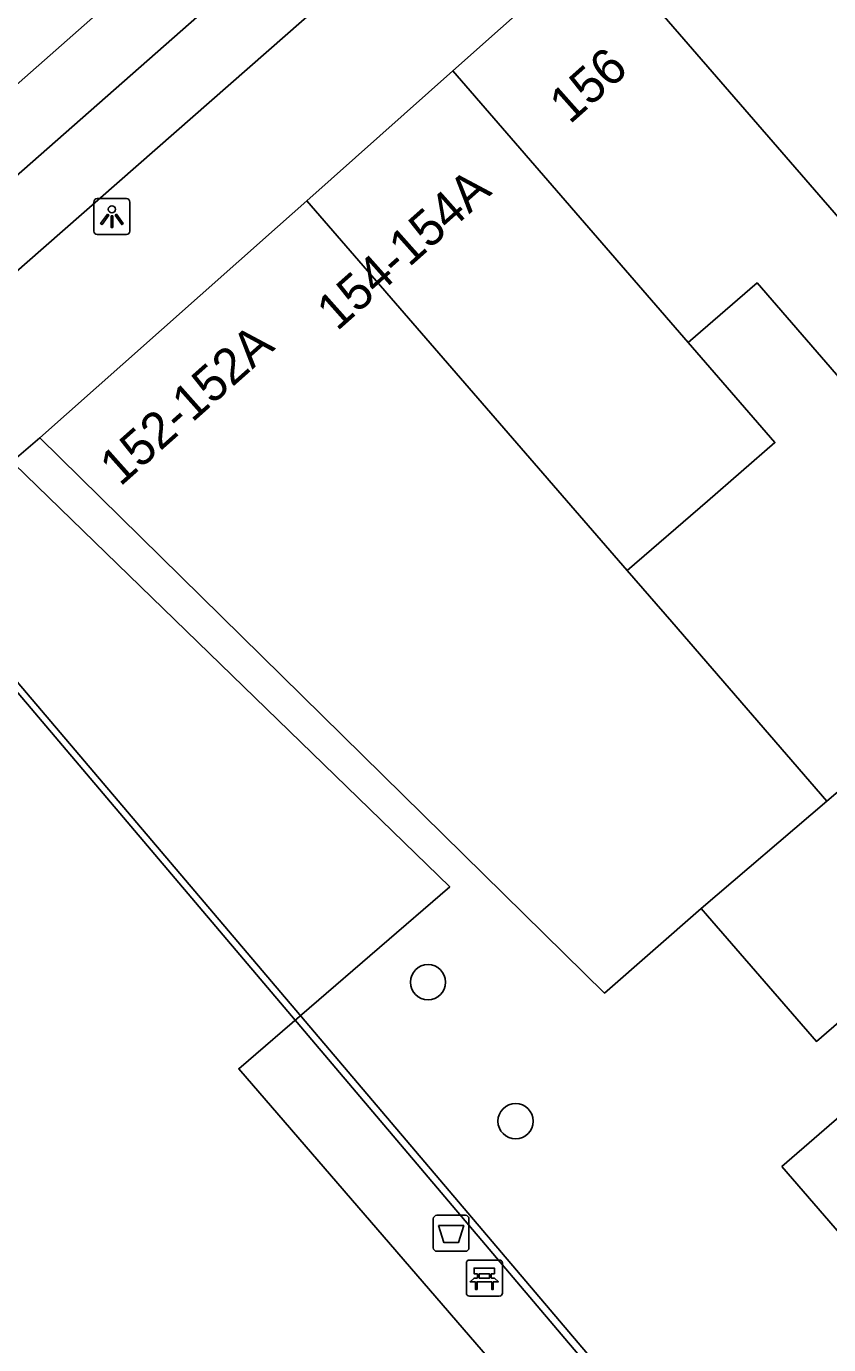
# Model space of a CAD drawing. Extents: x 162172 to 163187, y 382874 to 383684.
# Drawn here: x 162599.47 to 162621.75, y 383429.73 to 383466.36 of the extents above; entities that cross this region are included whole.
import ezdxf

# ---------------------------------------------------------------- set-up
doc = ezdxf.new("R2010")
doc.units = 0
for name, color, linetype in [('IMGEO_Afvalbak', 7, 'Continuous'), ('IMGEO_Bank', 7, 'Continuous'), ('IMGEO_Boom', 7, 'Continuous'), ('IMGEO_Lichtpunt', 7, 'Continuous'), ('IMGEO_Muur', 7, 'Continuous'), ('IMGEO_Pand', 7, 'Continuous'), ('IMGEO_Pand_nummerreeks', 7, 'Continuous'), ('IMGEO_Pand_vergunning_verleend', 7, 'Continuous'), ('IMGEO_Rijbaan_lokaal_gesloten', 7, 'Continuous'), ('IMGEO_Voetpad_open', 7, 'Continuous')]:
    doc.layers.add(name, color=color, linetype=linetype)

msp = doc.modelspace()

# ---------------------------------------------------------------- linework, layer by layer
at = {"layer": 'IMGEO_Afvalbak'}
for p, q in [((162610.771, 383432.422), (162610.771, 383433.222)), ((162610.771, 383433.222), (162610.771, 383432.422)), ((162610.871, 383433.322), (162611.661, 383433.322)), ((162611.661, 383433.322), (162610.871, 383433.322)), ((162611.761, 383433.222), (162611.761, 383432.422)), ((162611.761, 383432.422), (162611.761, 383433.222)), ((162611.661, 383432.322), (162610.871, 383432.322)), ((162610.871, 383432.322), (162611.661, 383432.322))]:
    msp.add_line(p, q, dxfattribs=at)
msp.add_lwpolyline([(162610.914, 383433.036), (162611.618, 383433.036), (162611.469, 383432.566), (162611.063, 383432.566), (162610.914, 383433.036)], dxfattribs=at)
for centre, start, end in [((162610.871, 383433.222), 90, 180), ((162610.871, 383433.222), 90, 180), ((162611.661, 383433.222), 0, 90), ((162611.661, 383433.222), 360, 90), ((162610.871, 383432.422), 180, 270), ((162610.871, 383432.422), 180, 270), ((162611.661, 383432.422), 270, 0), ((162611.661, 383432.422), 270, 0)]:
    msp.add_arc(centre, 0.1, start, end, dxfattribs=at)
at = {"layer": 'IMGEO_Bank'}
for p, q in [((162611.763, 383432.079), (162612.604, 383432.079)), ((162612.604, 383432.079), (162611.763, 383432.079)), ((162611.688, 383431.154), (162611.688, 383431.995)), ((162611.688, 383431.995), (162611.688, 383431.154)), ((162611.997, 383431.585), (162611.997, 383431.691)), ((162612.041, 383431.691), (162612.041, 383431.585)), ((162612.329, 383431.697), (162612.047, 383431.697)), ((162612.335, 383431.585), (162612.335, 383431.691)), ((162612.379, 383431.691), (162612.379, 383431.585)), ((162612.688, 383432.004), (162612.688, 383431.163)), ((162612.688, 383431.163), (162612.688, 383432.004)), ((162612.385, 383431.477), (162611.992, 383431.477)), ((162612.047, 383431.579), (162612.329, 383431.579)), ((162612.613, 383431.079), (162611.772, 383431.079)), ((162611.772, 383431.079), (162612.613, 383431.079))]:
    msp.add_line(p, q, dxfattribs=at)
for points in [[(162611.991, 383431.697), (162611.905, 383431.697), (162611.905, 383431.858), (162612.468, 383431.858), (162612.468, 383431.697), (162612.385, 383431.697)], [(162611.935, 383431.477), (162611.793, 383431.477), (162611.905, 383431.579), (162611.991, 383431.579)], [(162611.985, 383431.47), (162611.985, 383431.263), (162611.942, 383431.263), (162611.942, 383431.47)], [(162612.385, 383431.579), (162612.468, 383431.579), (162612.58, 383431.477), (162612.441, 383431.477)], [(162612.435, 383431.47), (162612.435, 383431.263), (162612.391, 383431.263), (162612.391, 383431.47)]]:
    msp.add_lwpolyline(points, dxfattribs=at)
for centre, radius, start, end in [((162611.766, 383432.001), 0.0779, 92.4484, 184.2845), ((162611.766, 383432.001), 0.0779, 92.4484, 184.2845), ((162612.61, 383432.001), 0.0779, 2.4484, 94.2845), ((162612.61, 383432.001), 0.0779, 2.4484, 94.2845), ((162611.99, 383431.69), 0.00671, 2.8957, 87.1043), ((162612.047, 383431.69), 0.00671, 92.8957, 177.1043), ((162612.329, 383431.69), 0.00671, 2.8957, 87.1043), ((162612.386, 383431.69), 0.00671, 92.8957, 177.1043), ((162611.935, 383431.47), 0.00671, 2.8957, 87.1043), ((162611.992, 383431.47), 0.00671, 92.8957, 177.1043), ((162611.99, 383431.586), 0.00671, 272.8957, 357.1043), ((162612.047, 383431.586), 0.00671, 182.8957, 267.1043), ((162612.329, 383431.586), 0.00671, 272.8957, 357.1043), ((162612.386, 383431.586), 0.00671, 182.8957, 267.1043), ((162612.384, 383431.47), 0.00671, 2.8957, 87.1043), ((162612.441, 383431.47), 0.00671, 92.8957, 177.1043), ((162611.766, 383431.157), 0.0779, 182.4484, 274.2845), ((162611.766, 383431.157), 0.0779, 182.4484, 274.2845), ((162612.61, 383431.157), 0.0779, 272.4484, 4.2845), ((162612.61, 383431.157), 0.0779, 272.4484, 4.2845)]:
    msp.add_arc(centre, radius, start, end, dxfattribs=at)
at = {"layer": 'IMGEO_Boom'}
for centre in [(162610.624, 383439.8), (162613.055, 383435.938)]:
    msp.add_circle(centre, 0.489, dxfattribs=at)
at = {"layer": 'IMGEO_Lichtpunt'}
for p, q in [((162601.346, 383461.478), (162601.346, 383460.671)), ((162601.346, 383461.478), (162601.346, 383460.671)), ((162602.248, 383461.573), (162601.44, 383461.573)), ((162602.248, 383461.573), (162601.44, 383461.573)), ((162602.342, 383460.671), (162602.342, 383461.478)), ((162602.342, 383460.671), (162602.342, 383461.478)), ((162601.44, 383460.577), (162602.248, 383460.577)), ((162601.44, 383460.577), (162602.248, 383460.577))]:
    msp.add_line(p, q, dxfattribs=at)
for points in [[(162601.72, 383461.142), (162601.759, 383461.114), (162601.571, 383460.852), (162601.533, 383460.879), (162601.72, 383461.142)], [(162601.822, 383461.094), (162601.869, 383461.094), (162601.869, 383460.772), (162601.822, 383460.772), (162601.822, 383461.094)], [(162601.932, 383461.114), (162601.97, 383461.141), (162602.157, 383460.879), (162602.118, 383460.851), (162601.932, 383461.114)]]:
    msp.add_lwpolyline(points, dxfattribs=at)
msp.add_circle((162601.845, 383461.276), 0.0994, dxfattribs=at)
for centre, start, end in [((162601.44, 383461.478), 90, 180), ((162601.44, 383461.478), 90, 180), ((162602.248, 383461.478), 0, 90), ((162602.248, 383461.478), 0, 90), ((162601.44, 383460.671), 180, 270), ((162601.44, 383460.671), 180, 270), ((162602.248, 383460.671), 270, 0), ((162602.248, 383460.671), 270, 360)]:
    msp.add_arc(centre, 0.0946, start, end, dxfattribs=at)
at = {"layer": 'IMGEO_Muur'}
for points in [[(162607.288, 383420.314), (162607.178, 383420.445), (162616.112, 383427.895), (162596.004, 383451.649)], [(162596.138, 383451.763), (162616.404, 383427.879), (162607.288, 383420.314)]]:
    msp.add_lwpolyline(points, dxfattribs=at)
at = {"layer": 'IMGEO_Pand'}
for points in [[(162611.314, 383465.123), (162615.371, 383468.732)], [(162615.371, 383468.732), (162625.527, 383457)], [(162611.314, 383465.123), (162607.258, 383461.515)], [(162617.848, 383457.576), (162611.314, 383465.123)], [(162607.258, 383461.515), (162606.442, 383460.789), (162602.153, 383456.972), (162599.848, 383454.93)], [(162616.152, 383451.241), (162607.258, 383461.515)], [(162625.527, 383457), (162623.337, 383455.104), (162619.762, 383459.233), (162617.848, 383457.576)], [(162617.848, 383457.576), (162620.256, 383454.794), (162618.381, 383453.17), (162616.152, 383451.241)], [(162599.848, 383454.93), (162615.52, 383439.496), (162618.211, 383441.85)], [(162618.211, 383441.85), (162618.387, 383441.647), (162621.409, 383438.156), (162631.002, 383446.461), (162630.617, 383446.905), (162632.963, 383448.937), (162634.081, 383447.646), (162636.73, 383449.94), (162640.509, 383453.212)], [(162621.702, 383444.831), (162617.39, 383449.812), (162616.152, 383451.241)], [(162621.702, 383444.831), (162626.082, 383448.572)], [(162618.211, 383441.85), (162621.702, 383444.831)], [(162620.447, 383434.677), (162622.821, 383431.935), (162627.453, 383435.945), (162625.079, 383438.687), (162620.447, 383434.677)]]:
    msp.add_lwpolyline(points, dxfattribs=at)
at = {"layer": 'IMGEO_Pand_vergunning_verleend'}
msp.add_lwpolyline([(162590.329, 383439.322), (162598.084, 383445.937), (162594.444, 383450.204), (162599.136, 383454.207), (162611.229, 383442.452), (162605.368, 383437.395), (162626.018, 383413.461), (162632.496, 383419.049), (162637.734, 383412.977), (162626.341, 383403.148), (162625.134, 383404.547), (162599.092, 383382.079), (162592.496, 383389.812), (162613.886, 383408.056), (162615.116, 383406.614), (162616.983, 383408.207), (162599.41, 383428.809), (162596.839, 383426.615), (162591.037, 383433.417), (162593.543, 383435.555), (162590.329, 383439.322)], dxfattribs=at)
at = {"layer": 'IMGEO_Rijbaan_lokaal_gesloten'}
for points in [[(162575.926, 383440.306), (162578.565, 383444.116), (162582.633, 383450.258), (162596.824, 383462.654), (162637.568, 383498.615), (162689.014, 383544.186), (162734.284, 383584.449), (162759.283, 383606.749), (162778.679, 383623.816), (162796.954, 383640.261), (162813.125, 383654.021), (162813.712, 383654.475)], [(162585.781, 383450.507), (162588.626, 383453.022), (162598.123, 383461.269), (162598.255, 383461.384), (162614.155, 383475.391), (162615.975, 383477.014)]]:
    msp.add_lwpolyline(points, dxfattribs=at)
at = {"layer": 'IMGEO_Voetpad_open'}
for points in [[(162589.892, 383451.377), (162599.492, 383459.81), (162608.692, 383467.892)], [(162596.138, 383451.763), (162599.848, 383454.93)]]:
    msp.add_lwpolyline(points, dxfattribs=at)

# ---------------------------------------------------------------- texts
at = {"layer": 'IMGEO_Pand_nummerreeks'}
for s, rotation, p in [('156', 41.6573, (162614.56, 383463.621)), ('154-154A', 41.654, (162608.098, 383457.873)), ('152-152A', 41.6655, (162602.076, 383453.556))]:
    msp.add_text(s, height=1, rotation=rotation, dxfattribs=at).set_placement(p)

doc.saveas('drawing.dxf')
